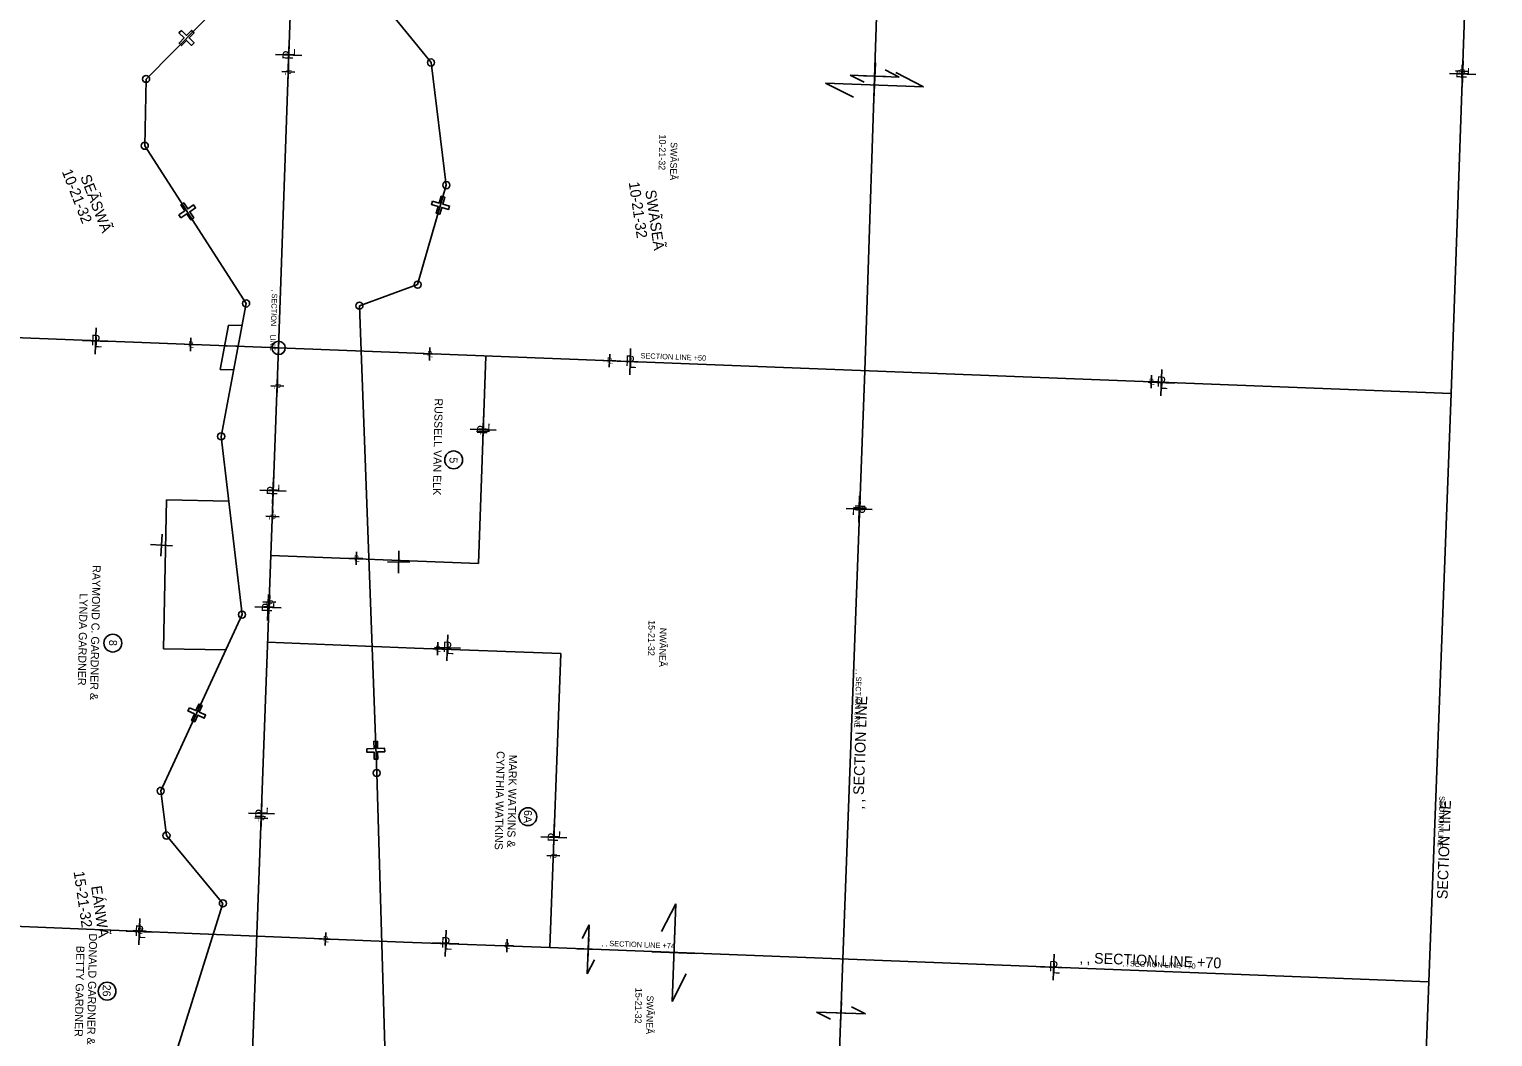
# Model space of a CAD drawing. Extents: x 2814293 to 2835768, y 121185 to 156337.
# Drawn here: x 2823143 to 2826435, y 139978 to 142244 of the extents above; entities that cross this region are included whole.
import ezdxf

# ---------------------------------------------------------------- set-up
doc = ezdxf.new("R2010")
doc.units = 0
for name, color, linetype in [('Default', 7, 'Continuous'), ('Photo-Retaining wall', 7, 'Continuous'), ('Roadway-Alignment notes', 7, 'Continuous'), ('Roadway-Ditches', 7, 'Continuous'), ('Roadway-Edge of pavement', 7, 'Continuous'), ('Roadway-Edge of shoulder', 7, 'Continuous'), ('Roadway-Entrances', 7, 'Continuous'), ('Roadway-New rw', 7, 'Continuous'), ('Roadway-Permanent easement', 7, 'Continuous'), ('Roadway-Safety', 7, 'Continuous'), ('Roadway-Temporary easement', 7, 'Continuous'), ('Roadway-Walls', 7, 'Continuous'), ('Scratch-2', 7, 'Continuous'), ('Scratch-4', 7, 'Continuous'), ('Scratch-5', 7, 'Continuous'), ('Text-New rw label', 7, 'Continuous'), ('Traffic_Control-Traffic barriers', 7, 'Continuous')]:
    doc.layers.add(name, color=color, linetype=linetype)

msp = doc.modelspace()

# ---------------------------------------------------------------- linework, layer by layer
at = {"layer": 'Default'}
for p, q in [((2823439.2, 141058.7), (2823441.8, 141108.6)), ((2823465.4, 141082.3), (2823415.5, 141084.9)), ((2823973.5, 141020.7), (2823974.5, 141070.7)), ((2823999, 141045.2), (2823949, 141046.2))]:
    msp.add_line(p, q, dxfattribs=at)
at = {"layer": 'Roadway-Ditches'}
for centre in [(2824097.5, 141275.3), (2823330.9, 140863.2), (2823330.9, 140863.2), (2824264.5, 140472.8), (2824264.5, 140472.8), (2823318, 140080.5)]:
    msp.add_circle(centre, 20, dxfattribs=at)
at = {"layer": 'Roadway-Edge of pavement'}
for p, q in [((2825045.6, 142163.4), (2825043.6, 142113.4)), ((2825068.4, 142152.2), (2825099.6, 142136.2)), ((2825099.6, 142136.2), (2824989.6, 142140.5)), ((2825020.8, 142124.5), (2824989.6, 142140.5)), ((2825019.6, 142139.3), (2825069.6, 142137.4)), ((2825044.6, 142138.4), (2825044.6, 142138.4)), ((2824386.5, 140198.6), (2824402.5, 140229.7)), ((2824398.2, 140119.8), (2824402.5, 140229.7)), ((2824425.3, 140173.8), (2824375.4, 140175.7)), ((2824401.3, 140199.7), (2824399.4, 140149.8)), ((2824400.4, 140174.7), (2824400.4, 140174.7)), ((2824414.2, 140150.9), (2824398.2, 140119.8)), ((2824969.8, 140056.5), (2824967.9, 140006.5)), ((2824992.7, 140045.4), (2825023.8, 140029.4)), ((2825023.8, 140029.4), (2824913.9, 140033.6)), ((2824945, 140017.6), (2824913.9, 140033.6)), ((2824943.8, 140032.5), (2824993.8, 140030.5)), ((2824968.8, 140031.5), (2824968.8, 140031.5))]:
    msp.add_line(p, q, dxfattribs=at)
at = {"layer": 'Roadway-Edge of shoulder'}
for p, q in [((2823725.4, 142156.3), (2823727.7, 142215.2)), ((2823697.1, 142186.9), (2823756, 142184.6)), ((2826337.7, 142144.2), (2826396.6, 142142)), ((2826366, 142113.7), (2826368.3, 142172.5)), ((2823293.6, 141572.1), (2823291.3, 141513.2)), ((2823263, 141543.8), (2823321.9, 141541.5)), ((2824495.6, 141525.6), (2824493.5, 141466.7)), ((2824465.1, 141497.2), (2824524, 141495.1)), ((2825690.4, 141478.4), (2825688.3, 141419.6)), ((2825659.9, 141450), (2825718.8, 141448)), ((2824162.9, 141313.9), (2824165, 141372.7)), ((2824134.5, 141344.4), (2824193.4, 141342.3)), ((2823690.2, 141176.7), (2823692.3, 141235.6)), ((2823661.8, 141207.2), (2823720.7, 141205.1)), ((2825010.7, 141194.2), (2825008.6, 141135.3)), ((2825039.1, 141163.7), (2824980.2, 141165.8)), ((2823678.8, 140913.9), (2823681, 140972.8)), ((2823650.5, 140944.5), (2823709.3, 140942.2)), ((2824084.6, 140882), (2824082.5, 140823.1)), ((2824054.1, 140853.6), (2824113, 140851.6)), ((2823664.3, 140450.7), (2823666.3, 140509.5)), ((2823635.9, 140481.1), (2823694.7, 140479.1)), ((2824321.9, 140397.1), (2824324, 140456)), ((2824293.5, 140427.6), (2824352.4, 140425.5)), ((2823391.6, 140243.6), (2823389.3, 140184.7)), ((2823361, 140215.3), (2823419.9, 140213)), ((2824080.7, 140217.4), (2824078.6, 140158.5)), ((2824050.2, 140189), (2824109.1, 140186.9)), ((2825417.6, 140135.4), (2825476.5, 140133.3)), ((2825448.1, 140163.8), (2825446, 140104.9))]:
    msp.add_line(p, q, dxfattribs=at)
at = {"layer": 'Roadway-Entrances'}
for p, q in [((2825111.4, 144144.8), (2825022.5, 141475.7)), ((2826434.8, 144063.6), (2826341.2, 141424.5)), ((2823750.1, 142846.6), (2823703.8, 141527.1)), ((2823703.8, 141527.1), (2821042.3, 141632.4)), ((2823605.3, 138881.7), (2823703.8, 141527.1)), ((2826341.2, 141424.5), (2823703.8, 141527.1)), ((2825022.5, 141475.7), (2824973.2, 140152.7)), ((2826341.2, 141424.5), (2826241.2, 138778.7)), ((2822324.3, 140259.5), (2823655.2, 140203.8)), ((2823984.6, 140191), (2823655.2, 140203.8)), ((2826291.2, 140101.6), (2824314.1, 140178.4)), ((2824973.2, 140152.7), (2824947.8, 139491))]:
    msp.add_line(p, q, dxfattribs=at)
msp.add_lwpolyline([(2824314.1, 140178.4), (2823984.6, 140191), (2823655.2, 140203.8)], dxfattribs=at)
at = {"layer": 'Roadway-New rw'}
for p, q in [((2824046.6, 142168.9), (2823875.8, 142378.6)), ((2823599.7, 142327.9), (2823405.7, 142131.8)), ((2824081, 141893.1), (2824046.6, 142168.9)), ((2823405.7, 142131.8), (2823402.7, 141981.8)), ((2823402.7, 141981.8), (2823630.6, 141627.1)), ((2824016.5, 141669.4), (2824081, 141893.1)), ((2823885.6, 141622), (2824016.5, 141669.4)), ((2823630.6, 141627.1), (2823574.6, 141328.2)), ((2823924.4, 140571), (2823885.6, 141622)), ((2823574.6, 141328.2), (2823621.5, 140927.2)), ((2823621.5, 140927.2), (2823438.5, 140530.8)), ((2823954.4, 139570.2), (2823924.4, 140571)), ((2823438.5, 140530.8), (2823451.5, 140430.5)), ((2823451.5, 140430.5), (2823578.5, 140277.9)), ((2823578.5, 140277.9), (2823375.5, 139631.9))]:
    msp.add_line(p, q, dxfattribs=at)
for points in [[(2823485.2, 142241.1), (2823479.6, 142235.4), (2823491, 142224.2), (2823479.8, 142212.8), (2823485.5, 142207.2), (2823496.7, 142218.5), (2823508.1, 142207.3), (2823513.7, 142213), (2823502.3, 142224.2), (2823513.5, 142235.6), (2823507.9, 142241.2), (2823496.6, 142229.9), (2823485.2, 142241.1)], [(2823479.5, 141826.5), (2823483.9, 141819.8), (2823497.2, 141828.7), (2823506.1, 141815.4), (2823512.8, 141819.9), (2823503.9, 141833.2), (2823517.2, 141842.1), (2823512.7, 141848.7), (2823499.4, 141839.8), (2823490.5, 141853.1), (2823483.9, 141848.7), (2823492.8, 141835.4), (2823479.5, 141826.5)], [(2824049.9, 141857.3), (2824047.6, 141849.7), (2824063, 141845.2), (2824058.5, 141829.8), (2824066.2, 141827.6), (2824070.7, 141843), (2824086.1, 141838.5), (2824088.3, 141846.2), (2824072.9, 141850.7), (2824077.4, 141866), (2824069.7, 141868.3), (2824065.2, 141852.9), (2824049.9, 141857.3)], [(2823503.2, 140717.9), (2823499.9, 140710.6), (2823514.5, 140704), (2823508, 140689.4), (2823515.3, 140686.2), (2823521.8, 140700.8), (2823536.5, 140694.3), (2823539.7, 140701.6), (2823525.1, 140708.1), (2823531.6, 140722.7), (2823524.3, 140726), (2823517.8, 140711.3), (2823503.2, 140717.9)], [(2823902.4, 140625.8), (2823902.6, 140617.8), (2823918.6, 140618.2), (2823919, 140602.2), (2823927, 140602.4), (2823926.6, 140618.4), (2823942.6, 140618.8), (2823942.3, 140626.8), (2823926.4, 140626.4), (2823925.9, 140642.4), (2823917.9, 140642.2), (2823918.4, 140626.2), (2823902.4, 140625.8)]]:
    msp.add_lwpolyline(points, close=True, dxfattribs=at)
at = {"layer": 'Roadway-Permanent easement'}
for p, q in [((2823590.9, 141577.9), (2823572.2, 141478.3)), ((2823621.3, 141577.3), (2823590.9, 141577.9)), ((2823612.5, 141530.7), (2823582.2, 141531.9)), ((2823602.6, 141477.7), (2823572.2, 141478.3))]:
    msp.add_line(p, q, dxfattribs=at)
at = {"layer": 'Roadway-Temporary easement'}
for p, q in [((2823451.7, 141185.2), (2823445, 140850.7)), ((2823591.7, 141182.4), (2823451.7, 141185.2)), ((2823445, 140850.7), (2823584.9, 140847.9))]:
    msp.add_line(p, q, dxfattribs=at)
at = {"layer": 'Roadway-Walls'}
for p, q in [((2823740.3, 142147.5), (2823710.9, 142148.6)), ((2823726.2, 142162.8), (2823725, 142133.3)), ((2826380.5, 142148.9), (2826351, 142149.9)), ((2826366.3, 142164.1), (2826365.2, 142134.7)), ((2823491.2, 141535.3), (2823520.6, 141534.2)), ((2823506.5, 141549.5), (2823505.3, 141520)), ((2824044, 141528.2), (2824042.9, 141498.7)), ((2824028.7, 141514), (2824058.1, 141512.9)), ((2824433.3, 141499), (2824462.7, 141498)), ((2824448.5, 141513.2), (2824447.5, 141483.8)), ((2823701.5, 141456.2), (2823700.4, 141426.7)), ((2825667.5, 141465.9), (2825666.5, 141436.4)), ((2823715.7, 141440.9), (2823686.2, 141442)), ((2825652.3, 141451.7), (2825681.7, 141450.6)), ((2824164.3, 141354), (2824163.3, 141324.6)), ((2824178.5, 141338.8), (2824149.1, 141339.8)), ((2823690.6, 141162.7), (2823689.6, 141133.3)), ((2825026, 141166.9), (2824996.6, 141167.9)), ((2825011.8, 141182.1), (2825010.8, 141152.7)), ((2823704.8, 141147.5), (2823675.4, 141148.5)), ((2823879.2, 141068.5), (2823878.1, 141039)), ((2823863.9, 141054.3), (2823893.4, 141053.2)), ((2823683.7, 140970.3), (2823682.6, 140940.9)), ((2823697.9, 140955.1), (2823668.4, 140956.1)), ((2824061.9, 140865.3), (2824060.9, 140835.9)), ((2824046.7, 140851.1), (2824076.1, 140850.1)), ((2823679.7, 140469), (2823650.3, 140470.1)), ((2823665.5, 140484.3), (2823664.5, 140454.8)), ((2824322.5, 140399.8), (2824321.5, 140370.4)), ((2824336.7, 140384.6), (2824307.3, 140385.6)), ((2823376.5, 140216.6), (2823406, 140215.5)), ((2823391.8, 140230.8), (2823390.7, 140201.3)), ((2823809.8, 140212.2), (2823808.8, 140182.8)), ((2823794.6, 140198), (2823824, 140197)), ((2824202.9, 140183.5), (2824232.3, 140182.5)), ((2824218.1, 140197.7), (2824217.1, 140168.3))]:
    msp.add_line(p, q, dxfattribs=at)
at = {"layer": 'Scratch-2'}
for p, q in [((2825046.2, 142168.5), (2825042.3, 142068.6)), ((2825091.9, 142146.3), (2825154.2, 142114.3)), ((2825154.2, 142114.3), (2824934.3, 142122.8)), ((2824996.6, 142090.8), (2824934.3, 142122.8)), ((2824994.3, 142120.5), (2825094.2, 142116.6)), ((2825044.2, 142118.5), (2825044.2, 142118.5)), ((2824565.2, 140215), (2824597.3, 140277.2)), ((2824588.7, 140057.4), (2824597.3, 140277.2)), ((2824594.9, 140217.3), (2824591.1, 140117.3)), ((2824643, 140165.4), (2824543, 140169.2)), ((2824593, 140167.3), (2824593, 140167.3)), ((2824620.8, 140119.6), (2824588.7, 140057.4))]:
    msp.add_line(p, q, dxfattribs=at)
at = {"layer": 'Scratch-4'}
for p, q in [((2823688.8, 141527.6), (2823703.8, 141527.1)), ((2823703.8, 141527.1), (2823703.3, 141512.1)), ((2823703.8, 141527.1), (2823704.3, 141542.1)), ((2823718.8, 141526.6), (2823703.8, 141527.1))]:
    msp.add_line(p, q, dxfattribs=at)
msp.add_circle((2823703.8, 141527.1), 15, dxfattribs=at)
for start, end in [(88.1, 178.1), (268.1, 358.1)]:
    msp.add_arc((2823703.8, 141527.1), 15, start, end, dxfattribs=at)
at = {"layer": 'Text-New rw label'}
for centre in [(2824046.6, 142168.9), (2823405.7, 142131.8), (2823402.7, 141981.8), (2824081, 141893.1), (2824016.5, 141669.4), (2823630.6, 141627.1), (2823885.6, 141622), (2823574.6, 141328.2), (2823621.5, 140927.2), (2823924.4, 140571), (2823438.5, 140530.8), (2823451.5, 140430.5), (2823578.5, 140277.9)]:
    msp.add_circle(centre, 8, dxfattribs=at)
at = {"layer": 'Traffic_Control-Traffic barriers'}
for p, q in [((2824153.1, 141042.3), (2824170.2, 141508.7)), ((2823686.4, 141060.4), (2824153.1, 141042.3)), ((2824338.7, 140839.5), (2824314.1, 140178.4))]:
    msp.add_line(p, q, dxfattribs=at)
msp.add_lwpolyline([(2823679.1, 140865.1), (2824009.1, 140852.2), (2824338.7, 140839.5)], dxfattribs=at)

# ---------------------------------------------------------------- texts
at = {"layer": 'Photo-Retaining wall'}
for s, p in [('10-21-32', (2824560.2, 142007.2)), ('SWÃSEÃ', (2824585.8, 141990.1)), ('15-21-32', (2824535.9, 140915)), ('NWÃNEÃ', (2824561.5, 140897.9)), ('15-21-32', (2824506.6, 140088)), ('SWÃNEÃ', (2824532.2, 140070.9))]:
    msp.add_text(s, height=15, rotation=268.849, dxfattribs=at).set_placement(p)
at = {"layer": 'Roadway-Alignment notes'}
for s, rotation, p in [('10-21-32', 291.4209, (2823215.8, 141923.8)), ('SEÃSWÃ', 291.4209, (2823257.1, 141911.6)), ('10-21-32', 278.3561, (2824491.3, 141899.3)), ('SWÃSEÃ', 278.3561, (2824528.4, 141881)), ('15-21-32', 278.3561, (2823242.6, 140349)), ('EÁNWÃ', 278.3561, (2823281.9, 140315.9))]:
    msp.add_text(s, height=24, rotation=rotation, dxfattribs=at).set_placement(p)
at = {"layer": 'Roadway-Ditches'}
for s, p in [('RUSSELL VAN ELK', (2824055.1, 141413.8)), ('5', (2824088.3, 141281.1)), ('RAYMOND C. GARDNER &', (2823285.6, 141038.8)), ('LYNDA GARDNER', (2823256.3, 140975)), ('8', (2823322.6, 140870.6)), ('CYNTHIA WATKINS', (2824194.3, 140620.4)), ('MARK WATKINS &', (2824222.1, 140612.3)), ('6A', (2824255.8, 140488)), ('DONALD GARDNER &', (2823277.7, 140210.2)), ('BETTY GARDNER', (2823249.1, 140182.4)), ('26', (2823308.5, 140095.3))]:
    msp.add_text(s, height=18, rotation=268.849, dxfattribs=at).set_placement(p)
at = {"layer": 'Roadway-Edge of shoulder'}
for s, rotation, p in [('P', 87.7804, (2823735.8, 142174.7)), ('L', 87.7804, (2823740.4, 142182.5)), ('P', 87.7804, (2826376.3, 142132.1)), ('L', 87.7804, (2826381, 142139.9)), ('P', 357.7804, (2823281.4, 141533.4)), ('L', 357.7804, (2823289.2, 141528.8)), ('P', 357.9775, (2824483.6, 141486.9)), ('L', 357.9775, (2824491.4, 141482.4)), ('P', 357.9775, (2825678.3, 141439.8)), ('L', 357.9775, (2825686.2, 141435.2)), ('L', 87.9775, (2824177.7, 141340.1)), ('P', 87.9775, (2824173.2, 141332.3)), ('P', 87.9775, (2823700.5, 141195.1)), ('L', 87.9775, (2823705.1, 141203)), ('L', 267.9775, (2824995.8, 141167.9)), ('P', 267.9775, (2825000.4, 141175.7)), ('P', 87.7804, (2823689.1, 140932.3)), ('L', 87.7804, (2823693.7, 140940.2)), ('P', 357.9775, (2824072.5, 140843.3)), ('L', 357.9775, (2824080.4, 140838.8)), ('P', 87.9775, (2823674.5, 140469.1)), ('L', 87.9775, (2823679.1, 140476.9)), ('P', 87.9775, (2824332.2, 140415.6)), ('L', 87.9775, (2824336.8, 140423.4)), ('P', 357.7804, (2823379.4, 140204.9)), ('L', 357.7804, (2823387.2, 140200.3)), ('P', 357.9775, (2824068.6, 140178.7)), ('L', 357.9775, (2824076.4, 140174.1)), ('P', 357.9775, (2825436, 140125.1)), ('L', 357.9775, (2825443.9, 140120.5))]:
    msp.add_text(s, height=23.6, rotation=rotation, dxfattribs=at).set_placement(p)
at = {"layer": 'Roadway-Safety'}
for s, rotation, p in [('‚ SECTION    LINE', 268.0989, (2823689, 141657.9)), ('SECTION LINE +50', 357.7804, (2824517.6, 141503.8)), ('‚ ‚ SECTION LINE', 267.9775, (2825003.4, 140804.8)), ('SECTION LINE', 267.9775, (2826315, 140519.5)), ('‚ ‚ SECTION LINE +74', 357.7804, (2824430.9, 140182.5)), ('‚ ‚ SECTION LINE +70', 357.7804, (2825602, 140137.1))]:
    msp.add_text(s, height=12, rotation=rotation, dxfattribs=at).set_placement(p)
at = {"layer": 'Roadway-Walls'}
for s, rotation, p in [('L', 267.7804, (2823718.7, 142149.7)), ('P', 267.7804, (2823721, 142153.6)), ('L', 267.9775, (2826358.8, 142151)), ('P', 267.9775, (2826361.1, 142154.9)), ('P', 357.7804, (2823500.4, 141530.1)), ('L', 357.7804, (2823504.3, 141527.8)), ('P', 357.9775, (2824037.9, 141508.8)), ('L', 357.9775, (2824041.8, 141506.5)), ('P', 357.9775, (2824442.5, 141493.9)), ('L', 357.9775, (2824446.4, 141491.6)), ('P', 357.9775, (2825661.5, 141446.5)), ('L', 357.9775, (2825665.4, 141444.2)), ('L', 267.7804, (2823694.1, 141443.1)), ('P', 267.7804, (2823696.4, 141447)), ('L', 267.9775, (2824156.9, 141340.9)), ('P', 267.9775, (2824159.2, 141344.8)), ('L', 267.9775, (2825004.4, 141169)), ('P', 267.9775, (2825006.7, 141172.9)), ('L', 267.9775, (2823683.2, 141149.6)), ('P', 267.9775, (2823685.5, 141153.5)), ('P', 357.9775, (2823873.2, 141049.1)), ('L', 357.9775, (2823877.1, 141046.8)), ('P', 267.9775, (2823678.5, 140961.1)), ('L', 267.9775, (2823676.2, 140957.2)), ('P', 357.9775, (2824055.9, 140846)), ('L', 357.9775, (2824059.8, 140843.7)), ('L', 267.9775, (2823658.1, 140471.1)), ('P', 267.9775, (2823660.4, 140475.1)), ('L', 267.9775, (2824315.1, 140386.7)), ('P', 267.9775, (2824317.4, 140390.6)), ('P', 357.9775, (2823385.8, 140211.4)), ('L', 357.9775, (2823389.7, 140209.1)), ('P', 357.9775, (2823803.8, 140192.9)), ('L', 357.9775, (2823807.7, 140190.6)), ('P', 357.9775, (2824212.1, 140178.4)), ('L', 357.9775, (2824216, 140176.1))]:
    msp.add_text(s, height=11.8, rotation=rotation, dxfattribs=at).set_placement(p)
at = {"layer": 'Scratch-5'}
for s, rotation, p in [('‚ ‚ SECTION LINE', 87.9775, (2825019, 140489.2)), ('SECTION LINE', 87.9775, (2826333.1, 140287)), ('‚ ‚ SECTION LINE +70', 357.7804, (2825505.7, 140144))]:
    msp.add_text(s, height=24, rotation=rotation, dxfattribs=at).set_placement(p)

doc.saveas('drawing.dxf')
